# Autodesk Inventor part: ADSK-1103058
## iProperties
Created: 2006-01
Part Number: ADSK-1103058
Document SubType Name: Modeling
Manufacturer: Standard
Standards Organization: Custom
Description: EXHAUST SEAL
Mass: 0.0308425 g
Surface Area: 0.98696 cm^2
Volume: 0.024674 cm^3
Density: 1.25 g/cm^3
Material: Silicone
Author: Autodesk, Inc.
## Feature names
1. Revolution1
